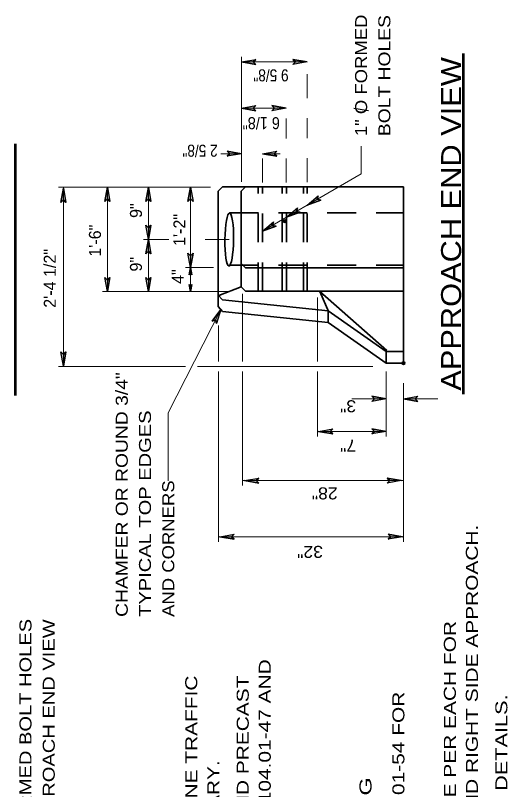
# Model space of a CAD drawing. Extents: x 12.6 to 19.5, y 6.1 to 16.3.
# Drawn here: x 16.942 to 19.401, y 12.348 to 16.213 of the extents above; entities that cross this region are included whole.
import ezdxf
from ezdxf.enums import TextEntityAlignment as Align

# ---------------------------------------------------------------- set-up
doc = ezdxf.new("R2010")
doc.units = 0
doc.header["$LTSCALE"] = 0.024
doc.header["$PDMODE"] = 32
doc.header["$PDSIZE"] = 0.012
doc.linetypes.add('DOT_DASHED', pattern=[7.7, 5, -1.2, 0.3, -1.2])
doc.linetypes.add('LONG_DASHED', pattern=[7.5, 6, -1.5])
for name, color, linetype, lineweight in [('1', 7, 'Continuous', 35), ('10', 7, 'Continuous', 25), ('12', 7, 'Continuous', 53), ('13', 7, 'Continuous', 53)]:
    doc.layers.add(name, color=color, linetype=linetype, lineweight=lineweight)

msp = doc.modelspace()

# ---------------------------------------------------------------- hatches: boundary and pattern name
at = {"layer": '10'}
for points in [[(18.1429, 15.9688), (18.0714, 15.9814), (18.1429, 15.994), (18.1294, 15.9814)], [(18.3281, 15.994), (18.3996, 15.9814), (18.3281, 15.9688), (18.3416, 15.9814)], [(18.1429, 15.738), (18.0714, 15.7506), (18.1429, 15.7632), (18.1294, 15.7506)], [(18.2231, 15.7632), (18.2946, 15.7506), (18.2231, 15.738), (18.2366, 15.7506)], [(17.9998, 15.5358), (18.0714, 15.5232), (17.9998, 15.5106), (18.0134, 15.5232)], [(18.2478, 15.5106), (18.1763, 15.5232), (18.2478, 15.5358), (18.2343, 15.5232)], [(17.169, 15.2796), (17.1816, 15.3511), (17.1942, 15.2796), (17.1816, 15.2931)], [(17.389, 15.2846), (17.4016, 15.3561), (17.4142, 15.2846), (17.4016, 15.2981)], [(17.5941, 15.2846), (17.6067, 15.3561), (17.6193, 15.2846), (17.6067, 15.2981)], [(17.804, 15.2847), (17.8166, 15.3562), (17.8292, 15.2847), (17.8166, 15.2982)], [(18.4677, 15.2912), (18.3996, 15.266), (18.455, 15.3129), (18.4497, 15.2953)], [(18.3644, 15.2309), (18.2963, 15.2057), (18.3517, 15.2526), (18.3464, 15.2349)], [(17.6193, 15.1664), (17.6067, 15.0949), (17.5941, 15.1664), (17.6067, 15.1529)], [(18.2444, 15.1607), (18.1763, 15.1355), (18.2317, 15.1824), (18.2264, 15.1648)], [(17.5941, 15.0234), (17.6067, 15.0949), (17.6193, 15.0234), (17.6067, 15.0369)], [(17.8292, 15.0261), (17.8166, 14.9546), (17.804, 15.0261), (17.8166, 15.0126)], [(17.8103, 14.9188), (17.8166, 14.9546), (17.8229, 14.9188), (17.8166, 14.9256)], [(17.4142, 14.9057), (17.4016, 14.8342), (17.389, 14.9057), (17.4016, 14.8922)], [(17.6193, 14.9057), (17.6067, 14.8342), (17.5941, 14.9057), (17.6067, 14.8922)], [(17.8229, 14.87), (17.8166, 14.8342), (17.8103, 14.87), (17.8166, 14.8632)], [(17.9246, 14.6874), (17.9682, 14.7454), (17.947, 14.676), (17.9419, 14.6937)], [(17.1942, 14.5336), (17.1816, 14.4621), (17.169, 14.5336), (17.1816, 14.5201)], [(18.7228, 14.3116), (18.7943, 14.299), (18.7228, 14.2864), (18.7363, 14.299)], [(18.9531, 14.2864), (18.8816, 14.299), (18.9531, 14.3116), (18.9396, 14.299)], [(18.5281, 14.1241), (18.4566, 14.1367), (18.5281, 14.1493), (18.5146, 14.1367)], [(18.7228, 14.1493), (18.7943, 14.1367), (18.7228, 14.1241), (18.7363, 14.1367)], [(18.1581, 13.8782), (18.0866, 13.8908), (18.1581, 13.9034), (18.1446, 13.8908)], [(18.7986, 13.9034), (18.8701, 13.8908), (18.7986, 13.8782), (18.8121, 13.8908)], [(18.0353, 13.5974), (17.9638, 13.61), (18.0353, 13.6226), (18.0218, 13.61)], [(18.8048, 13.6226), (18.8763, 13.61), (18.8048, 13.5974), (18.8183, 13.61)]]:
    msp.add_hatch(color=256, dxfattribs=at).paths.add_polyline_path(points)

# ---------------------------------------------------------------- linework, layer by layer
at = {"layer": '1'}
for p, q in [((17.9546, 15.336), (17.9763, 15.3577)), ((18.8811, 15.3577), (17.9763, 15.3577)), ((18.0704, 15.336), (18.0921, 15.3577)), ((18.8811, 14.4779), (18.8811, 15.3577)), ((17.9546, 14.7594), (17.9546, 15.336)), ((18.0704, 14.8583), (18.0704, 15.336)), ((18.0921, 14.9524), (18.0704, 14.9741)), ((18.8811, 14.9524), (18.0921, 14.9524)), ((18.0704, 14.8583), (17.9589, 14.8155)), ((18.0921, 14.8366), (18.0704, 14.8583)), ((17.9762, 14.7934), (17.9546, 14.8173)), ((18.8811, 14.8366), (18.0921, 14.8366)), ((18.508, 14.7311), (18.4625, 14.835)), ((18.7971, 14.5397), (18.4625, 14.835)), ((17.9762, 14.7934), (18.5047, 14.7377)), ((17.9546, 14.7594), (17.9762, 14.7354)), ((17.9762, 14.7354), (18.5047, 14.6798)), ((18.5047, 14.7377), (18.7943, 14.535)), ((18.5047, 14.6798), (18.5047, 14.7377)), ((18.5047, 14.6798), (18.7943, 14.4772)), ((18.8811, 14.535), (18.7943, 14.535)), ((18.7943, 14.4772), (18.7943, 14.535)), ((18.8811, 14.4772), (18.7943, 14.4772))]:
    msp.add_line(p, q, dxfattribs=at)
at = {"layer": '1', "linetype": 'LONG_DASHED'}
for p, q in [((18.1547, 14.8366), (18.1547, 15.3577)), ((18.1763, 14.8366), (18.1763, 15.3577)), ((18.2746, 14.8366), (18.2746, 15.3577)), ((18.2963, 14.8366), (18.2963, 15.3577)), ((18.3813, 14.8366), (18.3813, 15.3577)), ((18.3996, 14.8366), (18.3996, 15.3577)), ((18.012, 15.2274), (18.8811, 15.2274)), ((18.012, 14.9668), (18.8811, 14.9668))]:
    msp.add_line(p, q, dxfattribs=at)
at = {"layer": '1'}
msp.add_ellipse((18.01033, 15.09486), major_axis=(0.00169, 0.13252), ratio=0.163152, dxfattribs=at)
for p in [(18.2881, 15.1862), (18.8811, 14.4772)]:
    msp.add_point(p, dxfattribs=at)
at = {"layer": '10', "lineweight": 13}
for p, q in [((18.0714, 15.3827), (18.0714, 16.0064)), ((18.0714, 15.9814), (18.3996, 15.9814)), ((18.0714, 15.7506), (18.2946, 15.7506)), ((18.6691, 15.4234), (18.6691, 15.5609)), ((17.9681, 15.5232), (18.0714, 15.5232)), ((18.1763, 15.5232), (18.2646, 15.5232)), ((18.6691, 15.4234), (18.3996, 15.266)), ((17.9166, 15.3561), (17.1566, 15.3561)), ((17.1816, 15.3561), (17.1816, 14.461)), ((17.4016, 14.8342), (17.4016, 15.3561)), ((17.6067, 15.0949), (17.6067, 15.3561)), ((18.2963, 15.2057), (18.3996, 15.266)), ((18.1763, 15.1355), (18.2963, 15.2056)), ((18.2254, 15.1764), (18.1763, 15.1355)), ((18.236, 15.1583), (18.1763, 15.1355)), ((18.2254, 15.1764), (18.2239, 15.1634)), ((18.236, 15.1583), (18.2239, 15.1634)), ((17.5817, 15.0949), (17.7087, 15.0949)), ((17.6067, 15.0949), (17.6067, 14.8342)), ((17.9316, 14.9546), (17.7916, 14.9546)), ((18.0016, 14.8342), (17.3766, 14.8342)), ((18.0766, 14.8229), (18.0766, 14.486)), ((18.4516, 14.8051), (18.4516, 14.486)), ((17.9566, 14.6648), (17.9566, 14.486)), ((17.1566, 14.461), (17.7913, 14.461)), ((17.8512, 14.461), (18.7275, 14.461)), ((17.9566, 13.585), (17.9566, 14.436)), ((18.0766, 13.8658), (18.0766, 14.436)), ((18.4516, 14.1117), (18.4516, 14.436)), ((18.7943, 14.1117), (18.7943, 14.436)), ((18.8816, 14.3772), (18.8816, 13.585)), ((18.6236, 14.299), (18.7943, 14.299)), ((18.8816, 14.299), (19.0523, 14.299)), ((18.4516, 14.1367), (18.7943, 14.1367)), ((18.0766, 13.8908), (18.8816, 13.8908)), ((17.9566, 13.61), (18.8816, 13.61))]:
    msp.add_line(p, q, dxfattribs=at)
at = {"layer": '10', "linetype": 'DOT_DASHED', "lineweight": 13}
for p, q in [((18.3996, 15.381), (18.3996, 16.0064)), ((18.2946, 15.3794), (18.2946, 15.7756)), ((18.1763, 15.3794), (18.1763, 15.5482)), ((18.0102, 15.0949), (17.8603, 15.0949))]:
    msp.add_line(p, q, dxfattribs=at)
at = {"layer": '10'}
for p, q in [((18.0714, 15.9814), (18.1429, 15.994)), ((18.0714, 15.9814), (18.1429, 15.9688)), ((18.3996, 15.9814), (18.3281, 15.994)), ((18.3996, 15.9814), (18.3281, 15.9688)), ((18.0714, 15.7506), (18.1429, 15.7632)), ((18.0714, 15.7506), (18.1429, 15.738)), ((18.2946, 15.7506), (18.2231, 15.7632)), ((18.2946, 15.7506), (18.2231, 15.738)), ((18.7067, 15.7373), (18.6323, 15.7481)), ((18.0714, 15.5232), (17.9998, 15.5358)), ((18.0714, 15.5232), (17.9998, 15.5106)), ((18.1763, 15.5232), (18.2478, 15.5358)), ((18.1763, 15.5232), (18.2478, 15.5106)), ((17.1816, 15.3511), (17.169, 15.2796)), ((17.1816, 15.3511), (17.1942, 15.2796)), ((17.4016, 15.3561), (17.389, 15.2846)), ((17.4016, 15.3561), (17.4142, 15.2846)), ((17.6067, 15.3561), (17.5941, 15.2846)), ((17.6067, 15.3561), (17.6193, 15.2846)), ((17.8166, 15.3562), (17.804, 15.2847)), ((17.8166, 15.3562), (17.8292, 15.2847)), ((18.3996, 15.266), (18.455, 15.3129)), ((18.3996, 15.266), (18.4677, 15.2912)), ((18.2963, 15.2057), (18.3517, 15.2526)), ((18.2963, 15.2057), (18.3644, 15.2309)), ((17.6067, 15.0949), (17.5941, 15.1664)), ((17.6067, 15.0949), (17.6193, 15.1664)), ((18.1763, 15.1355), (18.2317, 15.1824)), ((18.1763, 15.1355), (18.2444, 15.1607)), ((17.6067, 15.0949), (17.5941, 15.0234)), ((17.6067, 15.0949), (17.6193, 15.0234)), ((17.8166, 14.9546), (17.804, 15.0261)), ((17.8166, 14.9546), (17.8292, 15.0261)), ((17.8166, 14.9546), (17.8103, 14.9188)), ((17.8166, 14.9546), (17.8229, 14.9188)), ((17.4016, 14.8342), (17.389, 14.9057)), ((17.4016, 14.8342), (17.4142, 14.9057)), ((17.6067, 14.8342), (17.5941, 14.9057)), ((17.6067, 14.8342), (17.6193, 14.9057)), ((17.8166, 14.8342), (17.8103, 14.87)), ((17.8166, 14.8342), (17.8229, 14.87)), ((17.9682, 14.7454), (17.9246, 14.6874)), ((17.9682, 14.7454), (17.947, 14.676)), ((17.1816, 14.4621), (17.169, 14.5336)), ((17.1816, 14.4621), (17.1942, 14.5336)), ((18.7943, 14.299), (18.7228, 14.3116)), ((18.8816, 14.299), (18.9531, 14.3116)), ((18.7943, 14.299), (18.7228, 14.2864)), ((18.8816, 14.299), (18.9531, 14.2864)), ((18.4566, 14.1367), (18.5281, 14.1493)), ((18.7943, 14.1367), (18.7228, 14.1493)), ((18.4566, 14.1367), (18.5281, 14.1241)), ((18.7943, 14.1367), (18.7228, 14.1241)), ((18.0866, 13.8908), (18.1581, 13.9034)), ((18.0866, 13.8908), (18.1581, 13.8782)), ((18.8701, 13.8908), (18.7986, 13.9034)), ((18.8701, 13.8908), (18.7986, 13.8782)), ((17.9638, 13.61), (18.0353, 13.6226)), ((17.9638, 13.61), (18.0353, 13.5974)), ((18.8763, 13.61), (18.8048, 13.6226)), ((18.8763, 13.61), (18.8048, 13.5974))]:
    msp.add_line(p, q, dxfattribs=at)
for points in [[(18.1429, 15.9688), (18.0714, 15.9814), (18.1429, 15.994), (18.1294, 15.9814)], [(18.3281, 15.994), (18.3996, 15.9814), (18.3281, 15.9688), (18.3416, 15.9814)], [(18.1429, 15.738), (18.0714, 15.7506), (18.1429, 15.7632), (18.1294, 15.7506)], [(18.2231, 15.7632), (18.2946, 15.7506), (18.2231, 15.738), (18.2366, 15.7506)], [(17.9998, 15.5358), (18.0714, 15.5232), (17.9998, 15.5106), (18.0134, 15.5232)], [(18.2478, 15.5106), (18.1763, 15.5232), (18.2478, 15.5358), (18.2343, 15.5232)], [(17.169, 15.2796), (17.1816, 15.3511), (17.1942, 15.2796), (17.1816, 15.2931)], [(17.389, 15.2846), (17.4016, 15.3561), (17.4142, 15.2846), (17.4016, 15.2981)], [(17.5941, 15.2846), (17.6067, 15.3561), (17.6193, 15.2846), (17.6067, 15.2981)], [(17.804, 15.2847), (17.8166, 15.3562), (17.8292, 15.2847), (17.8166, 15.2982)], [(18.4677, 15.2912), (18.3996, 15.266), (18.455, 15.3129), (18.4497, 15.2953)], [(18.3644, 15.2309), (18.2963, 15.2057), (18.3517, 15.2526), (18.3464, 15.2349)], [(17.6193, 15.1664), (17.6067, 15.0949), (17.5941, 15.1664), (17.6067, 15.1529)], [(18.2444, 15.1607), (18.1763, 15.1355), (18.2317, 15.1824), (18.2264, 15.1648)], [(17.5941, 15.0234), (17.6067, 15.0949), (17.6193, 15.0234), (17.6067, 15.0369)], [(17.8292, 15.0261), (17.8166, 14.9546), (17.804, 15.0261), (17.8166, 15.0126)], [(17.8103, 14.9188), (17.8166, 14.9546), (17.8229, 14.9188), (17.8166, 14.9256)], [(17.4142, 14.9057), (17.4016, 14.8342), (17.389, 14.9057), (17.4016, 14.8922)], [(17.6193, 14.9057), (17.6067, 14.8342), (17.5941, 14.9057), (17.6067, 14.8922)], [(17.8229, 14.87), (17.8166, 14.8342), (17.8103, 14.87), (17.8166, 14.8632)], [(17.9246, 14.6874), (17.9682, 14.7454), (17.947, 14.676), (17.9419, 14.6937)], [(17.1942, 14.5336), (17.1816, 14.4621), (17.169, 14.5336), (17.1816, 14.5201)], [(18.7228, 14.3116), (18.7943, 14.299), (18.7228, 14.2864), (18.7363, 14.299)], [(18.9531, 14.2864), (18.8816, 14.299), (18.9531, 14.3116), (18.9396, 14.299)], [(18.5281, 14.1241), (18.4566, 14.1367), (18.5281, 14.1493), (18.5146, 14.1367)], [(18.7228, 14.1493), (18.7943, 14.1367), (18.7228, 14.1241), (18.7363, 14.1367)], [(18.1581, 13.8782), (18.0866, 13.8908), (18.1581, 13.9034), (18.1446, 13.8908)], [(18.7986, 13.9034), (18.8701, 13.8908), (18.7986, 13.8782), (18.8121, 13.8908)], [(18.0353, 13.5974), (17.9638, 13.61), (18.0353, 13.6226), (18.0218, 13.61)], [(18.8048, 13.6226), (18.8763, 13.61), (18.8048, 13.5974), (18.8183, 13.61)]]:
    msp.add_lwpolyline(points, close=True, dxfattribs=at)
for points in [[(18.1429, 15.9688), (18.1294, 15.9814), (18.1429, 15.994)], [(18.3281, 15.994), (18.3416, 15.9814), (18.3281, 15.9688)], [(18.1429, 15.738), (18.1294, 15.7506), (18.1429, 15.7632)], [(18.2231, 15.7632), (18.2366, 15.7506), (18.2231, 15.738)], [(17.9998, 15.5358), (18.0134, 15.5232), (17.9998, 15.5106)], [(18.2478, 15.5106), (18.2343, 15.5232), (18.2478, 15.5358)], [(18.4677, 15.2912), (18.4497, 15.2953), (18.455, 15.3129)], [(17.169, 15.2796), (17.1816, 15.2931), (17.1942, 15.2796)], [(17.389, 15.2846), (17.4016, 15.2981), (17.4142, 15.2846)], [(17.5941, 15.2846), (17.6067, 15.2981), (17.6193, 15.2846)], [(17.804, 15.2847), (17.8166, 15.2982), (17.8292, 15.2847)], [(18.3644, 15.2309), (18.3464, 15.2349), (18.3517, 15.2526)], [(17.6193, 15.1664), (17.6067, 15.1529), (17.5941, 15.1664)], [(18.2444, 15.1607), (18.2264, 15.1648), (18.2317, 15.1824)], [(17.5941, 15.0234), (17.6067, 15.0369), (17.6193, 15.0234)], [(17.8292, 15.0261), (17.8166, 15.0126), (17.804, 15.0261)], [(17.8103, 14.9188), (17.8166, 14.9256), (17.8229, 14.9188)], [(17.4142, 14.9057), (17.4016, 14.8922), (17.389, 14.9057)], [(17.6193, 14.9057), (17.6067, 14.8922), (17.5941, 14.9057)], [(17.8229, 14.87), (17.8166, 14.8632), (17.8103, 14.87)], [(17.9246, 14.6874), (17.9419, 14.6937), (17.947, 14.676)], [(17.1942, 14.5336), (17.1816, 14.5201), (17.169, 14.5336)], [(18.7228, 14.3116), (18.7363, 14.299), (18.7228, 14.2864)], [(18.9531, 14.2864), (18.9396, 14.299), (18.9531, 14.3116)], [(18.5281, 14.1241), (18.5146, 14.1367), (18.5281, 14.1493)], [(18.7228, 14.1493), (18.7363, 14.1367), (18.7228, 14.1241)], [(18.1581, 13.8782), (18.1446, 13.8908), (18.1581, 13.9034)], [(18.7986, 13.9034), (18.8121, 13.8908), (18.7986, 13.8782)], [(18.0353, 13.5974), (18.0218, 13.61), (18.0353, 13.6226)], [(18.8048, 13.6226), (18.8183, 13.61), (18.8048, 13.5974)]]:
    msp.add_lwpolyline(points, dxfattribs=at)
at = {"layer": '10', "lineweight": 13}
for points in [[(17.8166, 14.8342), (17.8166, 14.9546), (17.8166, 15.3562)], [(17.7055, 13.8899), (17.7055, 14.2289), (17.9682, 14.7454)]]:
    msp.add_lwpolyline(points, dxfattribs=at)
at = {"layer": '12'}
for p, q in [((19.1814, 14.3219), (19.1814, 16.0229)), ((16.9421, 14.3156), (16.9421, 15.5718))]:
    msp.add_line(p, q, dxfattribs=at)

# ---------------------------------------------------------------- texts
for s, rotation, width, p in [('1" O FORMED', 90, 1.15, (18.6991, 15.6109)), ('BOLT HOLES', 90, 1.2, (18.8153, 15.6109)), ('9 5/8"', 180, 0.85, (18.307, 15.9444)), ('6 1/8"', 180, 0.9, (18.2634, 15.7056)), ('2 5/8"', 180, 0.85, (17.9525, 15.5681)), ('CHAMFER OR ROUND 3/4"', 90, 1.2, (17.5031, 13.21)), ('3"', 180, 1.1, (18.6445, 14.2918)), ('TYPICAL TOP EDGES', 90, 1.25, (17.6193, 13.21)), ('7"', 180, 1.1, (18.6445, 14.0954)), ('AND CORNERS', 90, 1.15, (17.7355, 13.21)), ('28"', 180, 1.1, (18.5522, 13.8567)), ('32"', 180, 1.1, (18.4789, 13.5646)), ('1" O FORMED BOLT HOLES', 90, 1.25, (17.0221, 11.8828)), ('SEE APPROACH END VIEW', 90, 1.25, (17.1383, 11.8828))]:
    msp.add_text(s, height=0.06, rotation=rotation, dxfattribs=dict(at, width=width)).set_placement(p)
at = {"layer": '12', "width": 1.15}
msp.add_text('APPROACH END VIEW', height=0.1, rotation=90, dxfattribs=at).set_placement((19.1688, 15.1724), align=Align.CENTER)
at = {"layer": '12'}
for s, p in [('9"', (17.5742, 15.2023)), ('1\'-2"', (17.7915, 15.0624)), ('1\'-6"', (17.3692, 15.0089)), ('2\'-4 1/2"', (17.1437, 14.7538)), ('9"', (17.5742, 14.9349)), ('4"', (17.7833, 14.8731))]:
    msp.add_text(s, height=0.06, rotation=90, dxfattribs=at).set_placement(p)
at = {"layer": '13'}
for s, width, p in [('  PRECAST TEMPORARY 32 INCH F SHAPE CONCRETE TRAFFIC BARRIER TERMINAL END RIGHT SIDE APPROACH.', 1.3, (19.2527, 7.8752)), ('6. THE COST OF THE CONNECTOR PIN SHALL BE INCIDENTAL TO THE CONTRACT PRICE PER EACH FOR', 1.3, (19.1427, 7.8752)), ('  TEMPORARY CONCRETE TRAFFIC BARRIER (PIN AND LOOP) AS SHOWN ON STD. MD 104.01-47 AND', 1.3, (18.2177, 7.8752)), ('1. THIS BARRIER SHALL BE USED IN ACCORDANCE WITH THE APPROPRIATE WORK ZONE TRAFFIC', 1.3, (17.8504, 7.8752)), ('2. THE BARRIER SHALL BE USED IN COMBINATION WITH TRAFFIC BARRIER W BEAM AND PRECAST', 1.3, (18.1077, 7.8752)), ('5. ONE CONNECTOR PIN SHALL BE FURNISHED WITH EACH BARRIER SEE STD. MD 104.01-54 FOR', 1.3, (18.8854, 7.8752)), ('7. SEE STD. MD 104.01-53 AND MD 104.01-54 FOR PIN AND LOOP JOINT CONNECTOR DETAILS.', 1.35, (19.4, 7.8752)), ('  CONTROL STANDARDS. REFER TO THE BOOK OF STANDARDS SECTION 1- PRELIMINARY.', 1.3, (17.9604, 7.8752)), ('               B) 2-NO.4 1/2" 0 REINFORCEMENT BARS - GRADE 60 - EACH 11\'-4" LONG', 1.45, (18.7212, 7.8752))]:
    msp.add_text(s, height=0.06, rotation=90, dxfattribs=dict(at, width=width)).set_placement(p)

doc.saveas('drawing.dxf')
